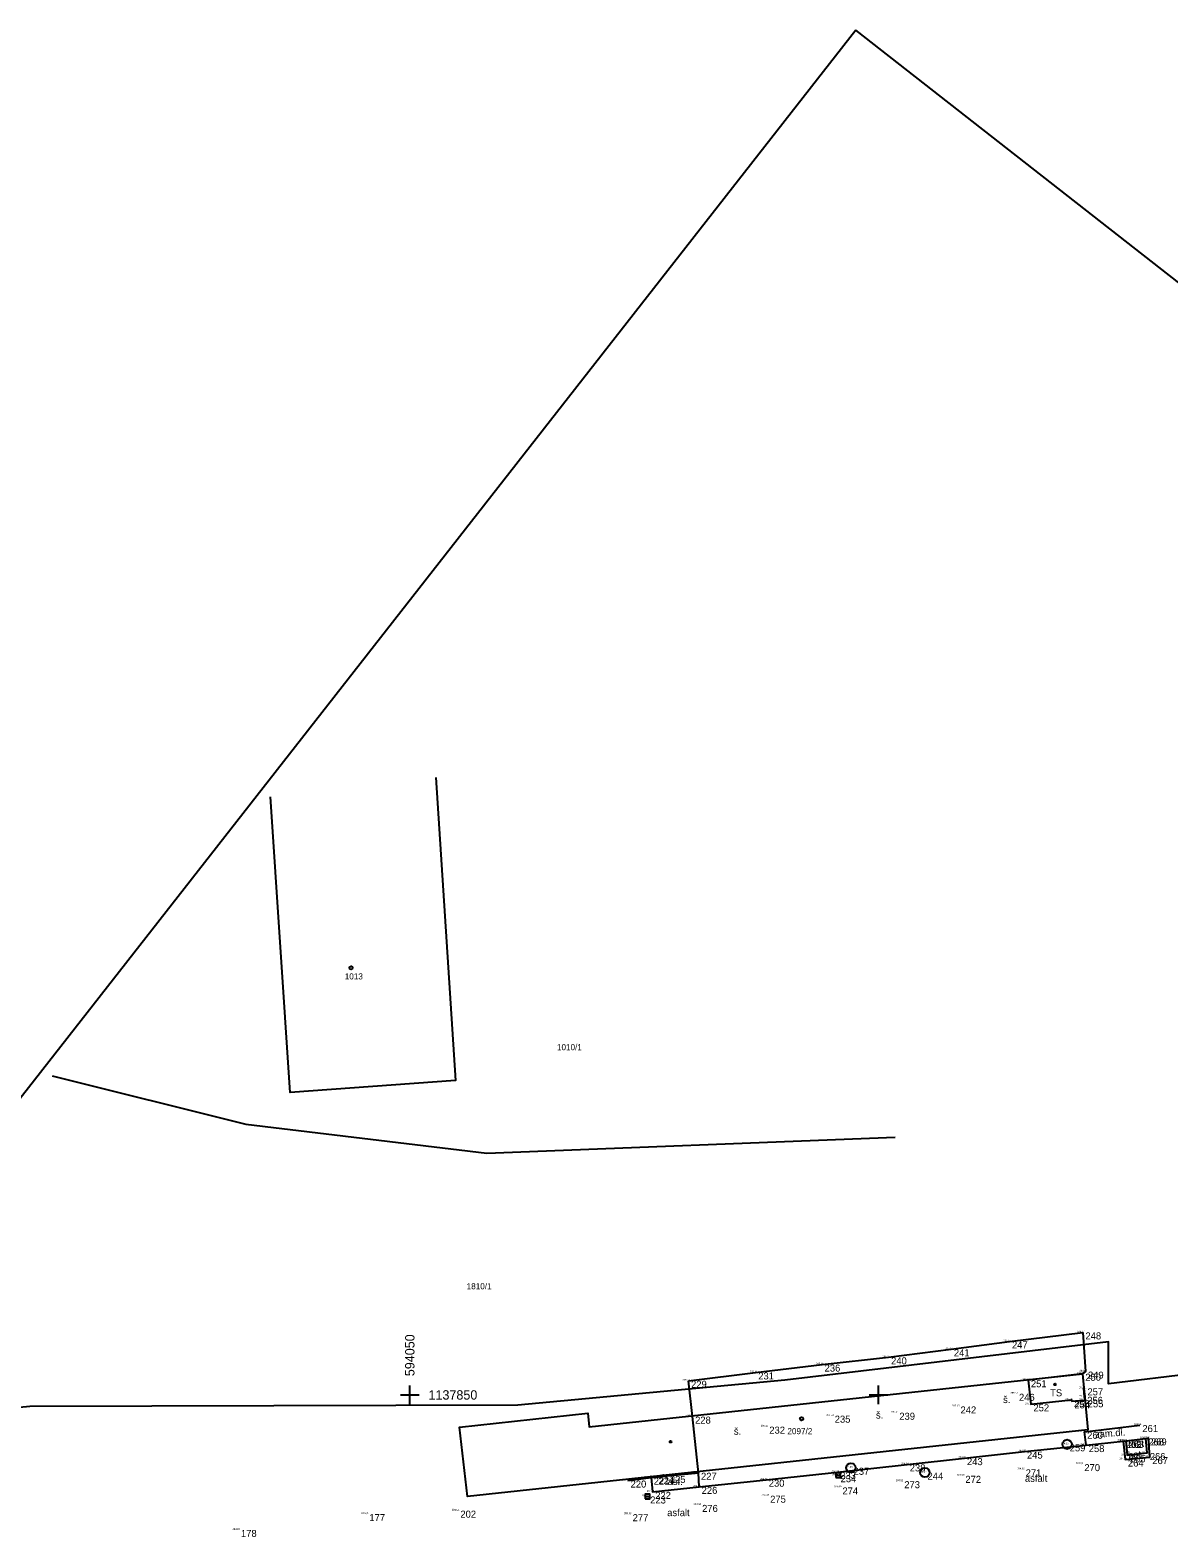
# Model space of a CAD drawing. Extents: x -594197 to -593885, y -1138044 to -1137704.
# Drawn here: x -594090.5 to -593969, y -1137865.2 to -1137704.4 of the extents above; entities that cross this region are included whole.
import ezdxf

# ---------------------------------------------------------------- set-up
doc = ezdxf.new("R2010")
doc.units = 0
for name, color, linetype in [('Budovy', 7, 'Continuous'), ('IS neurčené', 7, 'Continuous'), ('Katastrální mapa', 7, 'Continuous'), ('Ploty', 7, 'Continuous'), ('Podrobný bod', 7, 'Continuous'), ('Podrobný bod výška', 7, 'Continuous'), ('Podrobný bod číslo', 7, 'Continuous'), ('Polohopisné prvky', 7, 'Continuous'), ('Popisy', 7, 'Continuous'), ('Ram mapoveho listu', 7, 'Continuous'), ('Rozhraní ploch', 7, 'Continuous'), ('Vjezdy', 7, 'Continuous'), ('Značky budov', 7, 'Continuous'), ('Čtvercová síť', 7, 'Continuous')]:
    doc.layers.add(name, color=color, linetype=linetype)

msp = doc.modelspace()

# ---------------------------------------------------------------- linework, layer by layer
at = {"layer": 'Budovy'}
for points in [[(-594019.84, -1137852.31), (-594020.27, -1137848.49)], [(-593978.21, -1137847.74), (-593984.01, -1137848.43), (-593983.74, -1137851), (-593979.42, -1137850.54), (-593979.37, -1137850.68), (-593977.95, -1137850.57), (-593978, -1137850.2)], [(-593978.21, -1137847.74), (-593978.07, -1137849.29)], [(-594022.53, -1137858.64), (-594019.21, -1137858.3), (-594019.84, -1137852.31)], [(-594024.25, -1137858.82), (-594023.75, -1137858.76)]]:
    msp.add_lwpolyline(points, dxfattribs=at)
at = {"layer": 'IS neurčené'}
for p, q in [((-594004.56, -1137858.56), (-594004.06, -1137858.56)), ((-594024.88, -1137860.83), (-594024.38, -1137860.83))]:
    msp.add_line(p, q, dxfattribs=at)
for points in [[(-594004.56, -1137858.81), (-594004.06, -1137858.81), (-594004.06, -1137858.31), (-594004.56, -1137858.31)], [(-594024.88, -1137861.08), (-594024.38, -1137861.08), (-594024.38, -1137860.58), (-594024.88, -1137860.58)]]:
    msp.add_lwpolyline(points, close=True, dxfattribs=at)
for centre in [(-593979.87, -1137855.27), (-594002.93, -1137857.77), (-593995.04, -1137858.29)]:
    msp.add_circle(centre, 0.5, dxfattribs=at)
at = {"layer": 'Katastrální mapa'}
for points in [[(-594047.22, -1137784.15), (-594045.13, -1137816.47), (-594062.77, -1137817.75), (-594064.85, -1137786.2)], [(-594088.15, -1137815.98), (-594067.5, -1137821.11), (-594041.79, -1137824.21), (-593998.23, -1137822.49)], [(-593966.04, -1137847.69), (-593975.47, -1137848.8), (-593975.47, -1137844.32), (-594010, -1137848.42), (-594038.47, -1137851.11), (-594090.55, -1137851.25), (-594098.65, -1137852.01), (-594109.98, -1137851.34)], [(-593978.21, -1137847.74), (-593977.65, -1137853.72), (-594043.83, -1137860.85), (-594044.7, -1137853.45), (-594031.01, -1137851.93), (-594030.85, -1137853.42), (-593978.21, -1137847.74)]]:
    msp.add_lwpolyline(points, dxfattribs=at)
for centre in [(-594056.27, -1137804.45), (-594008.2, -1137852.54)]:
    msp.add_circle(centre, 0.175, dxfattribs=at)
at = {"layer": 'Ploty'}
msp.add_lwpolyline([(-593978.19, -1137843.33), (-593977.92, -1137847.51), (-593978.21, -1137847.74)], dxfattribs=at)
at = {"layer": 'Podrobný bod'}
for p, q in [((-593978.19, -1137843.33), (-593978.19, -1137843.33)), ((-593992.23, -1137845.13), (-593992.23, -1137845.13)), ((-593986.03, -1137844.29), (-593986.03, -1137844.29)), ((-594006.02, -1137846.76), (-594006.02, -1137846.76)), ((-593998.93, -1137845.99), (-593998.93, -1137845.99)), ((-594020.27, -1137848.49), (-594020.27, -1137848.49)), ((-594013.1, -1137847.6), (-594013.1, -1137847.6)), ((-593984.01, -1137848.43), (-593984.01, -1137848.43)), ((-593978.21, -1137847.74), (-593978.21, -1137847.74)), ((-593977.92, -1137847.51), (-593977.92, -1137847.51)), ((-593985.28, -1137849.88), (-593985.28, -1137849.88)), ((-593979.42, -1137850.54), (-593979.42, -1137850.54)), ((-593978, -1137850.2), (-593978, -1137850.2)), ((-593977.98, -1137849.29), (-593977.98, -1137849.29)), ((-593977.95, -1137850.57), (-593977.95, -1137850.57)), ((-594004.94, -1137852.21), (-594004.94, -1137852.21)), ((-593998.05, -1137851.9), (-593998.05, -1137851.9)), ((-593991.52, -1137851.23), (-593991.52, -1137851.23)), ((-593983.74, -1137851), (-593983.74, -1137851)), ((-593979.37, -1137850.68), (-593979.37, -1137850.68)), ((-594019.84, -1137852.31), (-594019.84, -1137852.31)), ((-594011.92, -1137853.38), (-594011.92, -1137853.38)), ((-593972.12, -1137853.21), (-593972.12, -1137853.21)), ((-593979.87, -1137855.27), (-593979.87, -1137855.27)), ((-593978.01, -1137853.93), (-593978.01, -1137853.93)), ((-593977.84, -1137855.35), (-593977.84, -1137855.35)), ((-593973.9, -1137854.92), (-593973.9, -1137854.92)), ((-593973.62, -1137854.89), (-593973.62, -1137854.89)), ((-593971.48, -1137854.64), (-593971.48, -1137854.64)), ((-593971.2, -1137854.63), (-593971.2, -1137854.63)), ((-593990.83, -1137856.74), (-593990.83, -1137856.74)), ((-593984.43, -1137856.04), (-593984.43, -1137856.04)), ((-593973.66, -1137856.89), (-593973.66, -1137856.89)), ((-593973.46, -1137856.44), (-593973.46, -1137856.44)), ((-593971.32, -1137856.19), (-593971.32, -1137856.19)), ((-593971.06, -1137856.63), (-593971.06, -1137856.63)), ((-594022.53, -1137858.64), (-594022.53, -1137858.64)), ((-594019.21, -1137858.3), (-594019.21, -1137858.3)), ((-594004.36, -1137858.23), (-594004.36, -1137858.23)), ((-594004.31, -1137858.56), (-594004.31, -1137858.56)), ((-594002.93, -1137857.77), (-594002.93, -1137857.77)), ((-593996.94, -1137857.41), (-593996.94, -1137857.41)), ((-593995.04, -1137858.29), (-593995.04, -1137858.29)), ((-593991, -1137858.63), (-593991, -1137858.63)), ((-593984.57, -1137857.94), (-593984.57, -1137857.94)), ((-593978.31, -1137857.38), (-593978.31, -1137857.38)), ((-594026.72, -1137859.13), (-594026.72, -1137859.13)), ((-594024.25, -1137858.82), (-594024.25, -1137858.82)), ((-594023.75, -1137858.76), (-594023.75, -1137858.76)), ((-594019.14, -1137859.81), (-594019.14, -1137859.81)), ((-594011.98, -1137859.04), (-594011.98, -1137859.04)), ((-594004.12, -1137859.87), (-594004.12, -1137859.87)), ((-593997.52, -1137859.2), (-593997.52, -1137859.2)), ((-594024.63, -1137860.83), (-594024.63, -1137860.83)), ((-594024.09, -1137860.34), (-594024.09, -1137860.34)), ((-594019.09, -1137861.73), (-594019.09, -1137861.73)), ((-594011.83, -1137860.75), (-594011.83, -1137860.75)), ((-594054.59, -1137862.71), (-594054.59, -1137862.71)), ((-594044.88, -1137862.34), (-594044.88, -1137862.34)), ((-594026.5, -1137862.72), (-594026.5, -1137862.72)), ((-594068.29, -1137864.4), (-594068.29, -1137864.4))]:
    msp.add_line(p, q, dxfattribs=at)
at = {"layer": 'Polohopisné prvky'}
msp.add_lwpolyline([(-594020.27, -1137848.49), (-594013.1, -1137847.6), (-594006.02, -1137846.76), (-593998.93, -1137845.99), (-593992.23, -1137845.13), (-593986.03, -1137844.29), (-593978.19, -1137843.33)], dxfattribs=at)
at = {"layer": 'Ram mapoveho listu'}
for p, q in [((-594002.41, -1137704.42), (-594196.55, -1137952.49)), ((-593885.47, -1137795.94), (-594002.41, -1137704.42))]:
    msp.add_line(p, q, dxfattribs=at)
at = {"layer": 'Rozhraní ploch'}
for points in [[(-593977.84, -1137855.35), (-593978.01, -1137853.93), (-593972.12, -1137853.21)], [(-594024.25, -1137858.82), (-594024.09, -1137860.34), (-594019.14, -1137859.81), (-594011.98, -1137859.04), (-594004.36, -1137858.23), (-593996.94, -1137857.41), (-593990.83, -1137856.74), (-593984.43, -1137856.04), (-593977.84, -1137855.35), (-593973.9, -1137854.92), (-593973.62, -1137854.89), (-593971.48, -1137854.64), (-593971.2, -1137854.63)], [(-593973.9, -1137854.92), (-593973.66, -1137856.89), (-593971.06, -1137856.63), (-593971.2, -1137854.63)], [(-593973.62, -1137854.89), (-593973.46, -1137856.44), (-593971.32, -1137856.19), (-593971.48, -1137854.64)], [(-594019.14, -1137859.81), (-594019.21, -1137858.3)]]:
    msp.add_lwpolyline(points, dxfattribs=at)
at = {"layer": 'Vjezdy'}
for points in [[(-593978, -1137850.2), (-593978.07, -1137849.29)], [(-594023.75, -1137858.76), (-594022.53, -1137858.64)], [(-594026.72, -1137859.13), (-594024.25, -1137858.82)]]:
    msp.add_lwpolyline(points, dxfattribs=at)
at = {"layer": 'Značky budov'}
for centre in [(-593981.16, -1137848.88), (-594022.18, -1137855)]:
    msp.add_circle(centre, 0.0875, dxfattribs=at)
at = {"layer": 'Čtvercová síť'}
for p, q in [((-594050, -1137851), (-594050, -1137849)), ((-594000, -1137851), (-594000, -1137849)), ((-594051, -1137850), (-594049, -1137850)), ((-594001, -1137850), (-593999, -1137850))]:
    msp.add_line(p, q, dxfattribs=at)

# ---------------------------------------------------------------- texts
at = {"layer": 'Katastrální mapa'}
for s, p in [('1013', (-594056.94, -1137805.68)), ('1010/1', (-594034.3, -1137813.23)), ('1810/1', (-594043.93, -1137838.73)), ('2097/2', (-594009.71, -1137854.19))]:
    msp.add_text(s, height=0.65, dxfattribs=at).set_placement(p)
at = {"layer": 'Podrobný bod výška'}
for s, p in [('285.17 ', (-593986.66, -1137844.29)), ('284.97 ', (-593978.82, -1137843.33)), ('285.12 ', (-593999.56, -1137845.99)), ('285.14 ', (-593992.86, -1137845.13)), ('285.11 ', (-594013.73, -1137847.6)), ('285.10 ', (-594006.65, -1137846.76)), ('284.89 ', (-593978.55, -1137847.51)), ('285.18 ', (-594020.9, -1137848.49)), ('285.23 ', (-593984.64, -1137848.43)), ('284.82 ', (-593978.84, -1137847.74)), ('285.12 ', (-593985.91, -1137849.88)), ('285.36 ', (-593980.05, -1137850.54)), ('285.10 ', (-593980, -1137850.68)), ('284.93 ', (-593978.63, -1137850.2)), ('285.21 ', (-593978.61, -1137849.29)), ('285.06 ', (-593978.58, -1137850.57)), ('285.06 ', (-594020.47, -1137852.31)), ('285.14 ', (-594005.57, -1137852.21)), ('285.11 ', (-593998.68, -1137851.9)), ('285.13 ', (-593992.15, -1137851.23)), ('285.28 ', (-593984.37, -1137851)), ('285.15 ', (-594012.55, -1137853.38)), ('284.94 ', (-593978.64, -1137853.93)), ('284.94 ', (-593972.75, -1137853.21)), ('284.93 ', (-593980.5, -1137855.27)), ('284.86 ', (-593978.47, -1137855.35)), ('284.86 ', (-593974.53, -1137854.92)), ('284.88 ', (-593974.25, -1137854.89)), ('284.90 ', (-593972.11, -1137854.64)), ('284.88 ', (-593971.83, -1137854.63)), ('284.89 ', (-593991.46, -1137856.74)), ('284.87 ', (-593985.06, -1137856.04)), ('284.89 ', (-593974.29, -1137856.89)), ('284.88 ', (-593974.09, -1137856.44)), ('284.88 ', (-593971.95, -1137856.19)), ('284.90 ', (-593971.69, -1137856.63)), ('284.96 ', (-594024.88, -1137858.82)), ('284.94 ', (-594024.38, -1137858.76)), ('284.98 ', (-594023.16, -1137858.64)), ('284.95 ', (-594019.84, -1137858.3)), ('284.85 ', (-594004.99, -1137858.23)), ('284.82 ', (-594004.94, -1137858.56)), ('284.88 ', (-594003.56, -1137857.77)), ('284.89 ', (-593997.57, -1137857.41)), ('284.87 ', (-593995.67, -1137858.29)), ('284.90 ', (-593991.63, -1137858.63)), ('284.89 ', (-593985.2, -1137857.94)), ('284.90 ', (-593978.94, -1137857.38)), ('284.95 ', (-594027.35, -1137859.13)), ('284.86 ', (-594024.72, -1137860.34)), ('284.84 ', (-594019.77, -1137859.81)), ('284.86 ', (-594012.61, -1137859.04)), ('284.90 ', (-594004.75, -1137859.87)), ('284.91 ', (-593998.15, -1137859.2)), ('284.82 ', (-594025.26, -1137860.83)), ('284.88 ', (-594019.72, -1137861.73)), ('284.89 ', (-594012.46, -1137860.75)), ('285.05 ', (-594055.22, -1137862.71)), ('284.88 ', (-594045.51, -1137862.34)), ('284.89 ', (-594027.13, -1137862.72)), ('284.87 ', (-594068.92, -1137864.4))]:
    msp.add_text(s, height=0.188, dxfattribs=at).set_placement(p)
at = {"layer": 'Podrobný bod číslo'}
for s, p in [(' 248', (-593978.19, -1137844.08)), (' 241', (-593992.23, -1137845.88)), (' 247', (-593986.03, -1137845.04)), (' 236', (-594006.02, -1137847.51)), (' 240', (-593998.93, -1137846.74)), (' 229', (-594020.27, -1137849.24)), (' 231', (-594013.1, -1137848.35)), (' 251', (-593984.01, -1137849.18)), (' 250', (-593978.21, -1137848.49)), (' 249', (-593977.92, -1137848.26)), (' 246', (-593985.28, -1137850.63)), (' 253', (-593979.42, -1137851.29)), (' 256', (-593978, -1137850.95)), (' 257', (-593977.98, -1137850.04)), (' 255', (-593977.95, -1137851.32)), (' 235', (-594004.94, -1137852.96)), (' 239', (-593998.05, -1137852.65)), (' 242', (-593991.52, -1137851.98)), (' 252', (-593983.74, -1137851.75)), (' 254', (-593979.37, -1137851.43)), (' 228', (-594019.84, -1137853.06)), (' 232', (-594011.92, -1137854.13)), (' 261', (-593972.12, -1137853.96)), (' 259', (-593979.87, -1137856.02)), (' 260', (-593978.01, -1137854.68)), (' 258', (-593977.84, -1137856.1)), (' 262', (-593973.9, -1137855.67)), (' 263', (-593973.62, -1137855.64)), (' 268', (-593971.48, -1137855.39)), (' 269', (-593971.2, -1137855.38)), (' 243', (-593990.83, -1137857.49)), (' 245', (-593984.43, -1137856.79)), (' 264', (-593973.66, -1137857.64)), (' 265', (-593973.46, -1137857.19)), (' 266', (-593971.32, -1137856.94)), (' 267', (-593971.06, -1137857.38)), (' 225', (-594022.53, -1137859.39)), (' 227', (-594019.21, -1137859.05)), (' 233', (-594004.36, -1137858.98)), (' 234', (-594004.31, -1137859.31)), (' 237', (-594002.93, -1137858.52)), (' 238', (-593996.94, -1137858.16)), (' 244', (-593995.04, -1137859.04)), (' 272', (-593991, -1137859.38)), (' 271', (-593984.57, -1137858.69)), (' 270', (-593978.31, -1137858.13)), (' 220', (-594026.72, -1137859.88)), (' 221', (-594024.25, -1137859.57)), (' 224', (-594023.75, -1137859.51)), (' 226', (-594019.14, -1137860.56)), (' 230', (-594011.98, -1137859.79)), (' 274', (-594004.12, -1137860.62)), (' 273', (-593997.52, -1137859.95)), (' 223', (-594024.63, -1137861.58)), (' 222', (-594024.09, -1137861.09)), (' 276', (-594019.09, -1137862.48)), (' 275', (-594011.83, -1137861.5)), (' 177', (-594054.59, -1137863.46)), (' 202', (-594044.88, -1137863.09)), (' 277', (-594026.5, -1137863.47)), (' 178', (-594068.29, -1137865.15))]:
    msp.add_text(s, height=0.75, dxfattribs=at).set_placement(p)
at = {"layer": 'Popisy'}
for s, p in [('š.', (-593986.7, -1137850.87)), ('TS', (-593981.68, -1137850.15)), ('š.', (-594000.26, -1137852.52)), ('š.', (-594015.42, -1137854.25)), ('asfalt', (-593984.37, -1137859.27)), ('asf.', (-594022.49, -1137859.61)), ('asfalt', (-594022.54, -1137862.93))]:
    msp.add_text(s, height=0.75, dxfattribs=at).set_placement(p)
for s, rotation, p in [('zám.dl.', 4.6669, (-593976.87, -1137854.59)), ('rošt', 4.2488, (-593973.32, -1137855.67)), ('bet.', 5.5778, (-593973.32, -1137856.8))]:
    msp.add_text(s, height=0.75, rotation=rotation, dxfattribs=at).set_placement(p)
at = {"layer": 'Čtvercová síť'}
msp.add_text('594050', height=1, rotation=90, dxfattribs=at).set_placement((-594049.5, -1137848))
msp.add_text('1137850', height=1, dxfattribs=at).set_placement((-594048, -1137850.5))

doc.saveas('drawing.dxf')
